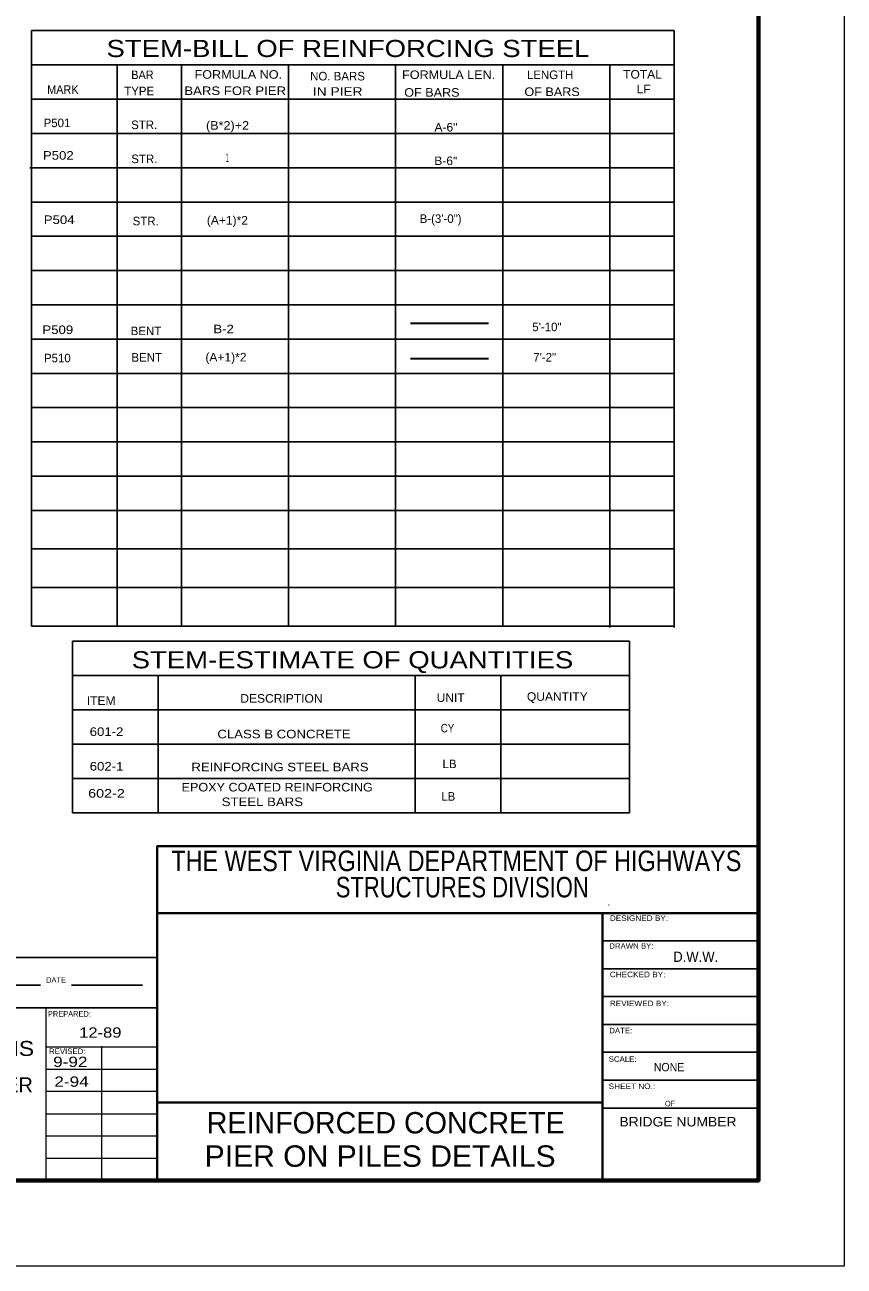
# Model space of a CAD drawing. Extents: x 3.64 to 6.84, y -0.8 to 1.19.
# Drawn here: x 6.045 to 6.842, y -0.795 to 0.413 of the extents above; entities that cross this region are included whole.
import ezdxf
from ezdxf.enums import TextEntityAlignment as Align

# ---------------------------------------------------------------- set-up
doc = ezdxf.new("R2010")
doc.units = 0
doc.header["$LTSCALE"] = 0.0033
doc.header["$PDMODE"] = 32
doc.header["$PDSIZE"] = 0.00165
doc.linetypes.add('DOTTED', pattern=[1.5, 0.3, -1.2])
doc.layers.add('1', color=7, linetype='Continuous', lineweight=40)

msp = doc.modelspace()

# ---------------------------------------------------------------- linework, layer by layer
at = {"layer": '1', "lineweight": 13}
for p, q in [((6.8415, 1.191917), (6.8415, -0.7945)), ((6.064917, -0.543333), (6.064917, -0.711333)), ((6.064917, -0.58125), (6.17325, -0.58125)), ((6.119083, -0.58075), (6.119083, -0.711333)), ((6.064917, -0.602917), (6.17325, -0.602917)), ((6.064917, -0.624583), (6.17325, -0.624583)), ((6.064917, -0.646333), (6.17325, -0.646333)), ((6.064917, -0.668), (6.17325, -0.668)), ((6.064917, -0.689667), (6.17325, -0.689667)), ((6.841583, -0.794667), (3.644833, -0.794667))]:
    msp.add_line(p, q, dxfattribs=at)
at = {"layer": '1', "lineweight": 25}
for p, q in [((6.051083, 0.40725), (6.051083, -0.172)), ((6.051083, 0.40725), (6.676083, 0.40725)), ((6.676083, 0.40725), (6.676083, -0.173417)), ((6.051083, 0.37375), (6.676083, 0.37375)), ((6.134417, 0.37375), (6.134417, -0.172833)), ((6.196917, 0.37375), (6.196917, -0.17225)), ((6.301083, 0.37375), (6.301083, -0.17225)), ((6.40525, 0.37375), (6.40525, -0.17225)), ((6.509417, 0.37375), (6.509417, -0.172833)), ((6.613583, 0.37375), (6.613583, -0.173417)), ((6.051083, 0.340417), (6.676083, 0.340417)), ((6.051083, 0.307083), (6.676083, 0.307083)), ((6.049583, 0.27375), (6.676083, 0.27375)), ((6.051083, 0.240417), (6.676083, 0.240417)), ((6.051083, 0.207083), (6.676083, 0.207083)), ((6.051083, 0.17375), (6.676083, 0.17375)), ((6.051083, 0.140417), (6.676083, 0.140417)), ((6.050333, 0.107083), (6.676083, 0.107083)), ((6.050333, 0.07375), (6.676083, 0.07375)), ((6.050333, 0.040417), (6.676083, 0.040417)), ((6.051917, 0.007083), (6.676083, 0.007083)), ((6.051083, -0.02625), (6.676083, -0.02625)), ((6.051083, -0.059583), (6.676083, -0.059583)), ((6.051083, -0.097083), (6.676083, -0.097083)), ((6.051083, -0.134583), (6.676083, -0.134583)), ((6.051083, -0.172083), (6.676083, -0.172083)), ((6.091, -0.18675), (6.091, -0.353583)), ((6.091, -0.18675), (6.632667, -0.18675)), ((6.632667, -0.18675), (6.632667, -0.353583)), ((6.091, -0.22025), (6.632667, -0.22025)), ((6.174333, -0.22025), (6.174333, -0.353583)), ((6.424333, -0.22025), (6.424333, -0.353583)), ((6.507667, -0.22025), (6.507667, -0.353583)), ((6.091, -0.253583), (6.632667, -0.253583)), ((6.091, -0.286917), (6.632667, -0.286917)), ((6.091, -0.32025), (6.632667, -0.32025)), ((6.091, -0.353583), (6.632667, -0.353583)), ((6.612583, -0.443667), (6.612583, -0.443167)), ((6.606583, -0.478333), (6.75825, -0.478333)), ((6.606583, -0.505417), (6.75825, -0.505417)), ((5.739917, -0.543333), (6.17325, -0.543333)), ((6.606583, -0.5325), (6.75825, -0.5325)), ((6.606583, -0.559583), (6.75825, -0.559583)), ((6.606583, -0.586667), (6.75825, -0.586667)), ((6.606583, -0.61375), (6.75825, -0.61375)), ((6.606583, -0.640917), (6.75825, -0.640917))]:
    msp.add_line(p, q, dxfattribs=at)
at = {"layer": '1', "lineweight": 35}
for p, q in [((6.419667, 0.122583), (6.495667, 0.122583)), ((6.419667, 0.088083), (6.495667, 0.088083))]:
    msp.add_line(p, q, dxfattribs=at)
at = {"layer": '1'}
for p, q in [((6.17325, -0.45125), (6.75825, -0.45125)), ((6.606583, -0.45125), (6.606583, -0.711333)), ((6.17325, -0.6355), (6.606583, -0.6355))]:
    msp.add_line(p, q, dxfattribs=at)
at = {"layer": '1', "linetype": 'DOTTED', "lineweight": 25}
for p, q in [((5.79375, -0.521417), (6.05975, -0.521417)), ((6.089917, -0.521417), (6.159083, -0.521417))]:
    msp.add_line(p, q, dxfattribs=at)
at = {"layer": '1', "lineweight": 70}
msp.add_line((3.811583, -0.711333), (6.75825, -0.711333), dxfattribs=at)
msp.add_lwpolyline([(6.75825, -0.711333), (6.75825, 1.10875), (3.811583, 1.10875), (3.811583, -0.711333)], dxfattribs=at)
at = {"layer": '1'}
msp.add_lwpolyline([(3.811583, -0.711333), (6.17325, -0.711333), (6.17325, -0.38625), (6.75825, -0.38625)], dxfattribs=at)
at = {"layer": '1', "lineweight": 25}
msp.add_lwpolyline([(5.739917, -0.711333), (5.739917, -0.494583), (6.17325, -0.494583)], dxfattribs=at)
at = {"layer": '1'}
msp.add_point((6.75825, -0.711333), dxfattribs=at)

# ---------------------------------------------------------------- texts
for s, height, width, p in [('STEM-BILL OF REINFORCING STEEL', 0.01667, 1.2, (6.124083, 0.381417)), ('BAR', 0.008334, 0.95, (6.148167, 0.36)), ('FORMULA NO.', 0.008334, 1.1, (6.20975, 0.360333)), ('FORMULA LEN.', 0.008334, 1.1, (6.411583, 0.360083)), ('TOTAL', 0.008334, 1.05, (6.626583, 0.3605)), ('MARK', 0.008334, 0.95, (6.066333, 0.345583)), ('BARS FOR PIER', 0.008334, 1.15, (6.19975, 0.3445)), ('IN PIER', 0.008334, 1.2, (6.324833, 0.34375)), ('OF BARS', 0.008334, 1.1, (6.413667, 0.342833)), ('OF BARS', 0.008334, 1.1, (6.530583, 0.3435)), ('LF', 0.008334, 1.05, (6.63975, 0.346083)), ('(B*2)+2', 0.008334, 1.1, (6.220833, 0.31075)), ('A-6"', 0.008334, 1.05, (6.443083, 0.309)), ('P502', 0.008334, 1.15, (6.06225, 0.281583)), ('B-6"', 0.008334, 1.05, (6.442917, 0.276333)), ('P504', 0.008334, 1.15, (6.063083, 0.219)), ('(A+1)*2', 0.008334, 1.05, (6.221667, 0.2185)), ('B-2', 0.008334, 1.15, (6.228, 0.11275)), ('P509', 0.008334, 1.15, (6.06175, 0.112)), ('STEM-ESTIMATE OF QUANTITIES', 0.01667, 1.2, (6.148583, -0.213167)), ('ITEM', 0.008334, 1.05, (6.104917, -0.248667)), ('DESCRIPTION', 0.008334, 1.05, (6.25425, -0.246583)), ('UNIT', 0.008334, 1.05, (6.445167, -0.245833)), ('QUANTITY', 0.008334, 1.05, (6.533, -0.24475)), ('601-2', 0.008334, 1.15, (6.10775, -0.278917)), ('CLASS B CONCRETE', 0.008334, 1.15, (6.231917, -0.28125)), ('CY', 0.008334, 0.85, (6.449167, -0.2755)), ('602-1', 0.008334, 1.15, (6.10775, -0.312583)), ('REINFORCING STEEL BARS', 0.008334, 1.15, (6.206667, -0.313333)), ('EPOXY COATED REINFORCING', 0.008334, 1.1, (6.197083, -0.332917)), ('602-2', 0.008334, 1.25, (6.10625, -0.338917)), ('STEEL BARS', 0.008334, 1.15, (6.236167, -0.347167)), ('DESIGNED BY:', 0.005418, 1.1, (6.613667, -0.458833)), ('DRAWN BY:', 0.005418, 1.05, (6.613083, -0.485917)), ('CHECKED BY:', 0.005418, 1.1, (6.613667, -0.513583)), ('REVIEWED BY:', 0.005418, 1.1, (6.613667, -0.54175)), ('DATE:', 0.005418, 1.05, (6.613083, -0.56825)), ('STANDARD BRIDGE PLANS', 0.01458, 1.15, (5.758417, -0.590167)), ('REVISED:', 0.005418, 1.05, (6.068167, -0.588333)), ('SCALE:', 0.005418, 1.05, (6.612583, -0.595917)), ('NONE', 0.008084, 0.95, (6.656417, -0.605083)), ('SHEET NO.:', 0.005418, 1.1, (6.612583, -0.622417)), ('OF', 0.005418, 0.9, (6.66725, -0.63925)), ('PIER ON PILES DETAILS', 0.02083, 1.05, (6.219583, -0.698))]:
    msp.add_text(s, height=height, dxfattribs=dict(at, width=width)).set_placement(p)
for s, height, p in [('NO. BARS', 0.008334, (6.322167, 0.358667)), ('LENGTH', 0.008334, (6.533, 0.36)), ('TYPE', 0.008334, (6.141333, 0.344167)), ('P501', 0.008334, (6.062917, 0.31325)), ('STR.', 0.008334, (6.148083, 0.311333)), ('STR.', 0.008334, (6.148167, 0.27825)), ('STR.', 0.008334, (6.1495, 0.21775)), ('B-(3\'-0")', 0.008334, (6.428667, 0.220083)), ('5\'-10"', 0.008334, (6.53825, 0.11475)), ('BENT', 0.008334, (6.147583, 0.110917)), ('P510', 0.008334, (6.06325, 0.0845)), ('BENT', 0.008334, (6.148333, 0.085083)), ('7\'-2"', 0.008334, (6.539167, 0.08525)), ('LB', 0.008334, (6.450917, -0.31025)), ('LB', 0.008334, (6.449667, -0.341917)), ('DATE', 0.005417, (6.065333, -0.519)), ('PREPARED:', 0.005418, (6.067083, -0.552)), ('REINFORCED CONCRETE PIER', 0.01458, (5.757833, -0.625583)), ('REINFORCED CONCRETE', 0.02083, (6.221583, -0.665583))]:
    msp.add_text(s, height=height, dxfattribs=at).set_placement(p)
for s, height, width, p in [('1', 0.008334, 0.4, (6.241625, 0.27925)), ('(A+1)*2', 0.008334, 1.05, (6.24025, 0.085333)), ('THE WEST VIRGINIA DEPARTMENT OF HIGHWAYS', 0.02, 0.85, (6.464375, -0.410417)), ('STRUCTURES DIVISION', 0.02, 0.8, (6.470125, -0.436)), ('D.W.W.', 0.01, 0.95, (6.697208, -0.498667)), ('12-89', 0.01, 1.2, (6.118083, -0.572417)), ('9-92', 0.01, 1.25, (6.088875, -0.600917)), ('2-94', 0.01, 1.25, (6.090042, -0.620167)), ('BRIDGE NUMBER', 0.009166, 1.1, (6.679917, -0.65875))]:
    msp.add_text(s, height=height, dxfattribs=dict(at, width=width)).set_placement(p, align=Align.CENTER)

doc.saveas('drawing.dxf')
